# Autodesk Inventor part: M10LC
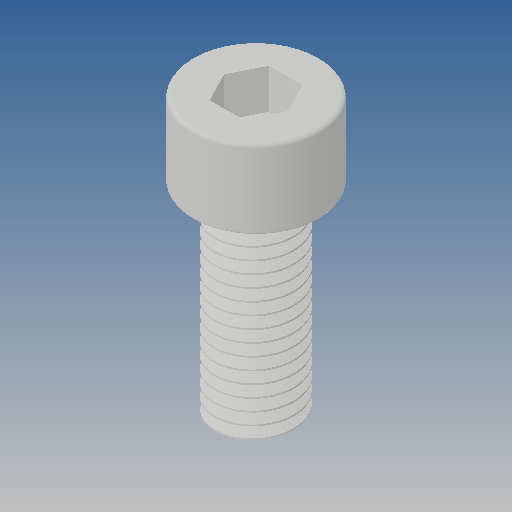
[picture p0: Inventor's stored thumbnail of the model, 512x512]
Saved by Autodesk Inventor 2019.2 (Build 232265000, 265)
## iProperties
Created: 2009-09
Part Number: M10LC
Material: Ogólny
Document SubType Name: Modeling
Designer: CADENGINEERING4
Density: 1 g/cm^3
Appearance: Domyślna
Author: CADENGINEERING4
Revision Number: 1LAST_VERSION
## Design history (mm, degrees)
feature "Baza1"
node "Bryła1"
